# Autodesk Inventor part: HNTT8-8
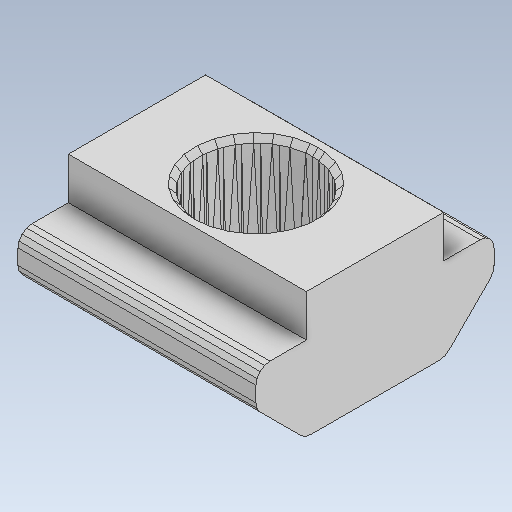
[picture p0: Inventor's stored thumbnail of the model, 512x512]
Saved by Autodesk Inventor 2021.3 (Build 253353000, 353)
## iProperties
Created: 2022-02
Part Number: HNTT8-8
Material: 一般
Document SubType Name: Modeling
Designer: kengo
Density: 1 g/cm^3
Appearance: 既定
Author: kengo
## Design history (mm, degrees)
feature "HNTT8-8"
node "ソリッド1"
